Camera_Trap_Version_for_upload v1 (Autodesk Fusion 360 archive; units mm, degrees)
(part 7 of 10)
offset_faces "OffsetFaces4" distance -2
position "Position37"
sketch "Sketch4" plane through (-21, 0, 0) normal (1, 0, 0) x axis (0, 1, 0)
  circle C1 centre (-38.4779, 86.3786) radius 7
  circle C2 centre (-38.4779, 86.3786) radius 5.075
  concentric C1 C2
  dimension "d1453" diameter C2 = 10.15
extrude "Extrude8" add sketch "Sketch4" along normal blind 4
sketch "Sketch5" plane through (-21, 0, 0) normal (1, 0, 0) x axis (0, 1, 0)
  circle C1 centre (-38.4779, 196.3786) radius 7
  circle C2 centre (-38.4779, 196.3786) radius 5.075
  concentric C1 C2
  dimension "d1456" diameter C2 = 10.15
extrude "Extrude9" add sketch "Sketch5" along normal blind 4
sketch "Battery_Cap" plane through (132, 0, 0) normal (1, 0, 0) x axis (0, 1, 0)
  curve K1 (30.3781, 72.1723) -> (-16.7801, 97.9933)
  curve K2 (-31.7648, 74.3864) -> (11.6713, 42.7017)
  line L1 (-24.6413, 218.3549) -> (-24.6413, 188.3549)
  line L2 (15.3587, 228.3549) -> (-14.6413, 228.3549)
  line L3 (25.3587, 188.3549) -> (25.3587, 218.3549)
  line L4 (-14.6413, 178.3549) -> (15.3587, 178.3549)
  curve K3 (-41.7381, 92.8101) -> (-42.0981, 81.8831)
  curve K4 (-35.4016, 81.8831) -> (-35.7616, 92.8101)
  curve K5 (-41.7381, 202.8101) -> (-42.0981, 191.8831)
  curve K6 (-35.4016, 191.8831) -> (-35.7616, 202.8101)
  line L5 (-18, 145) -> (-18, 127)
  line L6 (33, 153) -> (-10, 153)
  line L7 (41, 127) -> (41, 145)
  line L8 (-10, 119) -> (33, 119)
  line L9 (33, 28) -> (2.8201, 28)
  line L10 (53, 28) -> (33, 28)
  line L11 (53, 253.2053) -> (53, 28)
  line L12 (-35.395, 253.2053) -> (53, 253.2053)
  curve K7 (-35.395, 253.2053) -> (-39.3474, 235.851)
  line L13 (-24.9659, 145) -> (-24.9659, 127)
  line L14 (-10, 112.0341) -> (33, 112.0341)
  line L15 (47.9659, 127) -> (47.9659, 145)
  line L16 (33, 159.9659) -> (-10, 159.9659)
  line L17 (33, 152) -> (-10, 152)
  line L18 (-17, 145) -> (-17, 127)
  line L19 (-10, 120) -> (33, 120)
  line L20 (33, 151) -> (-10, 151)
  line L21 (-16, 145) -> (-16, 127)
  line L22 (-10, 121) -> (33, 121)
  line L23 (39, 135) -> (-16, 135)
  line L24 (41, 137.5) -> (39, 137.5)
  line L25 (39, 132.5) -> (41, 132.5)
  line L26 (39, 137.5) -> (39, 145)
  line L27 (39, 127) -> (39, 132.5)
  line L28 (40, 137.5) -> (40, 145)
  line L29 (40, 127) -> (40, 132.5)
  circle C1 centre (0.3587, 230.8549) radius 1
  circle C2 centre (-27.1413, 203.3549) radius 1
  circle C3 centre (0.3587, 175.8549) radius 1
  circle C4 centre (27.8587, 203.3549) radius 1
  arc A1 centre (0.3587, 70.5549) radius 30.0629 clockwise from (30.3781, 72.1723) to (11.6713, 42.7017)
  arc A2 centre (0.3587, 70.5549) radius 32.3513 clockwise from (-31.7648, 74.3864) to (-16.7801, 97.9933)
  arc A3 centre (-14.6413, 218.3549) radius 10 clockwise from (-24.6413, 218.3549) to (-14.6413, 228.3549)
  arc A4 centre (15.3587, 218.3549) radius 10 clockwise from (15.3587, 228.3549) to (25.3587, 218.3549)
  arc A5 centre (15.3587, 188.3549) radius 10 clockwise from (25.3587, 188.3549) to (15.3587, 178.3549)
  arc A6 centre (-14.6413, 188.3549) radius 10 clockwise from (-14.6413, 178.3549) to (-24.6413, 188.3549)
  arc A7 centre (-38.7498, 86.5785) radius 6.911 clockwise from (-41.7381, 92.8101) to (-35.7616, 92.8101)
  arc A8 centre (-38.7498, 86.5785) radius 5.767 clockwise from (-35.4016, 81.8831) to (-42.0981, 81.8831)
  arc A9 centre (-38.7498, 196.5785) radius 6.911 clockwise from (-41.7381, 202.8101) to (-35.7616, 202.8101)
  arc A10 centre (-38.7498, 196.5785) radius 5.767 clockwise from (-35.4016, 191.8831) to (-42.0981, 191.8831)
  circle C5 centre (39.9595, 118.7954) radius 1.4
  circle C6 centre (39.9595, 153.2046) radius 1.4
  circle C7 centre (-16.9412, 117.9586) radius 1.4
  circle C8 centre (-17.953, 152.353) radius 1.4
  arc A11 centre (-10, 127) radius 8 clockwise from (-10, 119) to (-18, 127)
  arc A12 centre (-10, 145) radius 8 clockwise from (-18, 145) to (-10, 153)
  arc A13 centre (33, 145) radius 8 clockwise from (33, 153) to (41, 145)
  arc A14 centre (33, 127) radius 8 clockwise from (41, 127) to (33, 119)
  arc A15 centre (0, 205) radius 50 clockwise from (-40.632, 175.8617) to (-39.3474, 235.851)
  arc A16 centre (-81.264, 146.7234) radius 50 clockwise from (-40.632, 175.8617) to (-31.815, 139.3208)
  arc A17 centre (-1.7685, 134.8228) radius 30.3814 clockwise from (-32.1436, 135.4388) to (-31.815, 139.3208)
  arc A18 centre (-82.1333, 136.4527) radius 50 clockwise from (-32.1436, 135.4388) to (-40.4895, 108.7798)
  arc A19 centre (2.8201, 80) radius 52 clockwise from (2.8201, 28) to (-40.4895, 108.7798)
  arc A20 centre (-10, 145) radius 14.9659 clockwise from (-24.9659, 145) to (-10, 159.9659)
  arc A21 centre (-10, 127) radius 14.9659 clockwise from (-10, 112.0341) to (-24.9659, 127)
  arc A22 centre (33, 127) radius 14.9659 clockwise from (47.9659, 127) to (33, 112.0341)
  arc A23 centre (33, 145) radius 14.9659 clockwise from (33, 159.9659) to (47.9659, 145)
  arc A24 centre (33, 145) radius 7 clockwise from (33, 152) to (40, 145)
  arc A25 centre (-10, 145) radius 7 clockwise from (-17, 145) to (-10, 152)
  arc A26 centre (-10, 127) radius 7 clockwise from (-10, 120) to (-17, 127)
  arc A27 centre (33, 127) radius 7 clockwise from (40, 127) to (33, 120)
  arc A28 centre (33, 145) radius 6 clockwise from (33, 151) to (39, 145)
  arc A29 centre (-10, 145) radius 6 clockwise from (-16, 145) to (-10, 151)
  arc A30 centre (-10, 127) radius 6 clockwise from (-10, 121) to (-16, 127)
  arc A31 centre (33, 127) radius 6 clockwise from (39, 127) to (33, 121)
  point P100 (-16, 135)
  point P101 (39, 135)
  point P104 (41, 132.5)
  point P106 (40, 137.5)
  point P107 (40, 132.5)
  coincident L21 P100
  coincident P101 L26
  perpendicular L23 L26
  horizontal L24
  horizontal L25
  coincident L7 P104
  concentric A13 A28
  concentric A12 A29
  concentric A11 A30
  concentric A14 A31
  tangent L22 A31
  tangent A31 L26
  tangent A30 L22
  tangent A29 L21
  tangent L20 A29
  tangent L21 A30
  tangent A28 L20
  tangent A28 L26
  collinear L26 L27
  concentric A13 A24
  concentric A12 A25
  concentric A11 A26
  concentric A14 A27
  tangent A26 L19
  tangent L19 A27
  tangent L17 A25
  tangent A24 L17
  tangent L18 A26
  tangent A25 L18
  tangent A27 L28
  tangent A24 L28
  coincident L24 P106
  coincident L25 P107
  collinear L28 L29
  dimension "d1459" = -6.9659
extrude "Extrude20" new body sketch "Battery_Cap" profile of C5 C6 C7 C8 A11 L5 A12 L6 A13 L7 A14 L8 L16 A23 A22 A20 L15 L13 A21 L14 along normal blind 3 bodies "Battery_lid_complete"
extrude "Extrude21" new body sketch "Battery_Cap" profile of A24 A27 L17 L18 A26 L29 A25 L19 L22 A31 A29 L20 L27 A30 L21 A28 L24 L25 against normal blind 15 bodies "Battery_lid_wall"
fillet "Fillet1" radius 0.5
combine "Combine15"
extrude "Extrude22" cut of existing geometry blind -5
extrude "Extrude23" cut of existing geometry blind -5
sketch "Sketch2" plane through (0, 31, 0) normal (0, -1, 0) x axis (1, 0, 0)
  line L1 (66, 245) -> (66, 158)
  line L2 (120, 245) -> (66, 245)
  line L3 (120, 158) -> (120, 245)
  line L4 (66, 158) -> (120, 158)
  line L5 (123, 155) -> (63, 155)
  line L6 (123, 248) -> (123, 155)
  line L7 (63, 248) -> (123, 248)
  line L8 (63, 155) -> (63, 248)
  line L9 (123, 248) -> (63, 248)
  line L10 (63, 155) -> (123, 155)
  line L11 (63, 248) -> (63, 155)
  line L12 (114, 158) -> (114, 158)
  line L13 (120, 158) -> (120, 158)
  line L14 (120, 245) -> (66, 245)
  line L15 (120, 158) -> (120, 245)
  line L16 (66, 158) -> (120, 158)
  line L17 (66, 245) -> (66, 158)
  line L18 (66.5, 158.5) -> (119.5, 158.5)
  line L19 (66.5, 244.5) -> (66.5, 158.5)
  line L20 (119.5, 244.5) -> (66.5, 244.5)
  line L21 (119.5, 158.5) -> (119.5, 244.5)
  line L22 (123, 248) -> (63, 248)
  line L23 (123, 155) -> (123, 248)
  line L24 (63, 155) -> (123, 155)
  line L25 (63, 248) -> (63, 155)
  line L26 (105.3133, 127.0783) -> (105.3133, 145.0783)
  line L27 (125.3133, 145.0783) -> (125.3133, 135.0783)
  line L28 (125.3133, 135.0783) -> (125.3133, 127.0783)
  line L29 (105.3133, 145.0783) -> (105.3133, 158.6452)
  line L30 (125.3133, 158.6452) -> (105.3133, 158.6452)
  line L31 (125.3133, 158.6452) -> (125.3133, 145.0783)
  line L32 (105.3133, 113.5114) -> (105.3133, 127.0783)
  line L33 (125.3133, 127.0783) -> (125.3133, 113.5114)
  line L34 (125.3133, 113.5114) -> (105.3133, 113.5114)
  circle C1 centre (69, 242) radius 1.5
  circle C2 centre (117, 242) radius 1.5
  circle C3 centre (117, 161) radius 1.5
  circle C4 centre (69, 161) radius 1.5
  point P7 (123, 155)
  point P12 (123, 155)
  point P9 (63, 248)
  point P10 (63, 248)
  point P16 (114, 158)
  point P5 (120, 158)
  point P14 (120, 158)
  point P3 (66, 245)
  point P18 (66, 245)
  horizontal L9
  horizontal L10
  vertical L11
  coincident P7 P12
  coincident P9 P10
  coincident L4 P16
  coincident P5 P14
  horizontal L14
  vertical L15
  horizontal L16
  vertical L17
  coincident P3 P18
  horizontal L22
  vertical L23
  horizontal L24
  vertical L25
  dimension "d1473" = 0.5
extrude "Extrude5" cut of existing geometry to an object
extrude "Extrude6" add of existing geometry to an object
extrude "Extrude10" new body sketch "Sketch2" profile of L1 L2 L3 L4 L5 L6 L7 L8 L9 L10 L11 L14 L15 L16 L17 L19 L20 L18 L21 C1 C2 C3 C4 L22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 along normal blind 3
extrude "Extrude11" new body sketch "Sketch2" profile of L19 L20 L18 L21 C1 C2 C3 C4 against normal blind 2.7 bodies "Electronic_lid"
combine "Combine7"
fillet "Fillet1" radius 0.5
combine "Combine8"
sketch "Sketch10" plane through (-17.1975, 0, 0) normal (-1, 0, 0) x axis (0, -1, 0)
  line L1 (-18, 105) -> (-45.508, 105)
  line L2 (-15, 176.0417) -> (-15, 108)
  line L3 (-45.508, 179.0417) -> (-18, 179.0417)
  line L4 (-48.508, 108) -> (-48.508, 176.0417)
  line L5 (-15, 174.0406) -> (-48.508, 174.0406)
  line L6 (-15.297, 174.0406) -> (-48.297, 174.0406)
  line L7 (-15.297, 117.0406) -> (-15.297, 174.0406)
  line L8 (-48.297, 117.0406) -> (-15.297, 117.0406)
  line L9 (-48.297, 174.0406) -> (-48.297, 117.0406)
  circle C1 centre (-19, 176.786) radius 1.4
  circle C2 centre (-45, 107.4) radius 1.4
  circle C3 centre (-45, 176.786) radius 1.4
  circle C4 centre (-19, 107.4) radius 1.4
  arc A1 centre (-45.508, 108) radius 3 clockwise from (-45.508, 105) to (-48.508, 108)
  arc A2 centre (-18, 108) radius 3 clockwise from (-15, 108) to (-18, 105)
  arc A3 centre (-18, 176.0417) radius 3 clockwise from (-18, 179.0417) to (-15, 176.0417)
  arc A4 centre (-45.508, 176.0417) radius 3 clockwise from (-48.508, 176.0417) to (-45.508, 179.0417)
  point P18 (-48.508, 174.0406)
  point P19 (-15, 174.0406)
  point P20 (-48.297, 174.0406)
  point P21 (-15.297, 174.0406)
  point P23 (-48.297, 117.0406)
  coincident L4 P18
  coincident L2 P19
  perpendicular L2 L5
  horizontal L6
  vertical L7
  horizontal L8
  vertical L9
  coincident L5 P20
  dimension "d1484" distance P20 P21 = 33
  dimension "d1485" distance P20 P23 = 57
extrude "Extrude10" cut sketch "Sketch10" profile of L5 L6 L7 L8 L9 against normal blind 2
sketch "Sketch11" plane through (-17.1975, 0, 0) normal (-1, 0, 0) x axis (0, -1, 0)
  line L1 (-15.297, 117.0406) -> (-15.297, 174.0406)
  line L2 (-48.297, 117.0406) -> (-15.297, 117.0406)
  line L3 (-48.297, 174.0406) -> (-48.297, 117.0406)
  line L4 (-15.297, 174.0406) -> (-48.297, 174.0406)
  line L5 (-18, 105) -> (-45.508, 105)
  line L6 (-15, 176.0417) -> (-15, 108)
  line L7 (-45.508, 179.0417) -> (-18, 179.0417)
  line L8 (-48.508, 108) -> (-48.508, 176.0417)
  line L9 (-21, 117.0406) -> (-41.6953, 117.0406)
  line L10 (-21, 110.57) -> (-21, 117.0406)
  line L11 (-41.6953, 110.57) -> (-21, 110.57)
  line L12 (-41.6953, 117.0406) -> (-41.6953, 110.57)
  circle C1 centre (-19, 176.786) radius 1.4
  circle C2 centre (-45, 107.4) radius 1.4
  circle C3 centre (-45, 176.786) radius 1.4
  circle C4 centre (-19, 107.4) radius 1.4
  arc A1 centre (-45.508, 108) radius 3 clockwise from (-45.508, 105) to (-48.508, 108)
  arc A2 centre (-18, 108) radius 3 clockwise from (-15, 108) to (-18, 105)
  arc A3 centre (-18, 176.0417) radius 3 clockwise from (-18, 179.0417) to (-15, 176.0417)
  arc A4 centre (-45.508, 176.0417) radius 3 clockwise from (-48.508, 176.0417) to (-45.508, 179.0417)
  point P22 (-41.6953, 117.0406)
  horizontal L9
  vertical L10
  horizontal L11
  vertical L12
  coincident L2 P22
extrude "Extrude11" cut sketch "Sketch11" profile of L2 L9 L10 L11 L12 against normal blind 4
external_derived "ExternalDerived5"
modify "Modify1"
modify "Modify2"
modify "Modify3"
modify "Modify4"
external_derived "ExternalDerived6"
move "Move7"
move_face "MoveFace1"
move "Move8"
move "Move9"
sketch "Sketch12" plane through (-23.4, 0, 0) normal (-1, 0, 0) x axis (0, -1, 0)
  line L1 (-35.3087, 168.4587) -> (-22.4913, 168.4587)
  line L2 (-35.3087, 135.6413) -> (-35.3087, 168.4587)
  line L3 (-22.4913, 135.6413) -> (-35.3087, 135.6413)
  line L4 (-22.4913, 168.4587) -> (-22.4913, 135.6413)
  line L5 (-21, 170) -> (-37, 170)
  line L6 (-21, 134) -> (-21, 170)
  line L7 (-37, 134) -> (-21, 134)
  line L8 (-37, 170) -> (-37, 134)
  line L9 (-30.895, 154.3118) -> (-27.4, 154.3118)
  curve K1 (-30.895, 154.3118) -> (-33.6332, 157.05)
  line L10 (-33.6332, 160.45) -> (-33.6332, 157.05)
  curve K2 (-33.6332, 160.45) -> (-30.895, 163.1882)
  line L11 (-27.4, 163.1882) -> (-30.895, 163.1882)
  curve K3 (-27.4, 163.1882) -> (-24.6618, 160.45)
  line L12 (-24.6618, 157.05) -> (-24.6618, 160.45)
  curve K4 (-24.6618, 157.05) -> (-27.4, 154.3118)
  line L13 (-30.8586, 142.0634) -> (-27.3636, 142.0755)
  curve K5 (-30.8586, 142.0634) -> (-33.6062, 144.7922)
  line L14 (-33.6179, 148.1921) -> (-33.6062, 144.7922)
  curve K6 (-33.6179, 148.1921) -> (-30.8892, 150.9398)
  line L15 (-27.3942, 150.9518) -> (-30.8892, 150.9398)
  curve K7 (-27.3942, 150.9518) -> (-24.6466, 148.2231)
  line L16 (-24.6348, 144.8231) -> (-24.6466, 148.2231)
  curve K8 (-24.6348, 144.8231) -> (-27.3636, 142.0755)
  horizontal L5
  vertical L6
  horizontal L7
  vertical L8
extrude "Extrude12" add of existing geometry blind 3
sketch "Sketch13" plane through (-20.1975, 0, 0) normal (-1, 0, 0) x axis (0, -1, 0)
  line L1 (-41.6953, 117.0406) -> (-41.6953, 110.57)
  line L2 (-48.297, 117.0406) -> (-41.6953, 117.0406)
  line L3 (-48.297, 174.0406) -> (-48.297, 117.0406)
  line L4 (-15.297, 174.0406) -> (-48.297, 174.0406)
  line L5 (-15.297, 117.0406) -> (-15.297, 174.0406)
  line L6 (-21, 117.0406) -> (-15.297, 117.0406)
  line L7 (-21, 110.57) -> (-21, 117.0406)
  line L8 (-41.6953, 110.57) -> (-21, 110.57)
  curve K1 (36.0257, 253.4503) -> (39.9781, 236.096)
  line L9 (-52.3693, 253.4503) -> (36.0257, 253.4503)
  line L10 (-52.3693, 28.245) -> (-52.3693, 253.4503)
  line L11 (-32.3693, 28.245) -> (-52.3693, 28.245)
  line L12 (-2.1894, 28.245) -> (-32.3693, 28.245)
  line L13 (-34.3693, 194.245) -> (-34.3693, 213.245)
  line L14 (-41.3693, 194.245) -> (-34.3693, 194.245)
  line L15 (-41.3693, 213.245) -> (-41.3693, 194.245)
  line L16 (-34.3693, 213.245) -> (-41.3693, 213.245)
  line L17 (-16.019, 180) -> (-47, 180)
  line L18 (-13.019, 107.5562) -> (-13.019, 177)
  line L19 (-48, 104.5562) -> (-16.019, 104.5562)
  line L20 (-50, 177) -> (-50, 106.5562)
  line L21 (-21, 170) -> (-37, 170)
  line L22 (-21, 134) -> (-21, 170)
  line L23 (-37, 134) -> (-21, 134)
  line L24 (-37, 170) -> (-37, 134)
  circle C1 centre (-19, 107.4) radius 1.4
  circle C2 centre (-45, 176.786) radius 1.4
  circle C3 centre (-45, 107.4) radius 1.4
  circle C4 centre (-19, 176.786) radius 1.4
  arc A1 centre (-2.1894, 80.245) radius 52 clockwise from (41.1202, 109.0248) to (-2.1894, 28.245)
  arc A2 centre (82.764, 136.6977) radius 50 clockwise from (41.1202, 109.0248) to (32.7743, 135.6838)
  arc A3 centre (2.3992, 135.0677) radius 30.3814 clockwise from (32.4457, 139.5658) to (32.7743, 135.6838)
  arc A4 centre (81.8947, 146.9684) radius 50 clockwise from (32.4457, 139.5658) to (41.2627, 176.1067)
  arc A5 centre (0.6307, 205.245) radius 50 clockwise from (39.9781, 236.096) to (41.2627, 176.1067)
  arc A6 centre (-47, 177) radius 3 clockwise from (-50, 177) to (-47, 180)
  arc A7 centre (-16.019, 177) radius 3 clockwise from (-16.019, 180) to (-13.019, 177)
  arc A8 centre (-16.019, 107.5562) radius 3 clockwise from (-13.019, 107.5562) to (-16.019, 104.5562)
  arc A9 centre (-48, 106.5562) radius 2 clockwise from (-48, 104.5562) to (-50, 106.5562)
  horizontal L17
  vertical L18
  horizontal L19
  vertical L20
  tangent L17 A6
  tangent L20 A6
  tangent L17 A7
  tangent L18 A7
  tangent L18 A8
  tangent L19 A8
  tangent L20 A9
  tangent L19 A9
  horizontal L21
  vertical L22
  horizontal L23
  vertical L24
  dimension "d1492" radius A6 = 3
  dimension "d1493" radius A7 = 3
  dimension "d1494" radius A8 = 3
  dimension "d1495" radius A9 = 2
extrude "Extrude5" add sketch "Sketch12" along normal blind 1
extrude "Extrude7" add sketch "Sketch13" profile of C1 C2 C3 C4 L1 L2 L3 L4 L5 L6 L7 L8 L17 L18 L19 L20 A6 A7 A8 A9 L21 L22 L23 L24 against normal blind 3
sketch "Sketch14" plane through (-17.1975, 0, 0) normal (1, 0, 0) x axis (0, 1, 0)
  line L1 (21, 134) -> (37, 134)
  line L2 (21, 170) -> (21, 134)
  line L3 (37, 170) -> (21, 170)
  line L4 (37, 134) -> (37, 170)
  line L5 (16.019, 180) -> (47, 180)
  line L6 (13.019, 107.5562) -> (13.019, 177)
  line L7 (48, 104.5562) -> (16.019, 104.5562)
  line L8 (50, 177) -> (50, 106.5562)
  circle C1 centre (45, 107.4) radius 1.4
  circle C2 centre (19, 176.7861) radius 1.4
  circle C3 centre (19, 107.4) radius 1.4
  circle C4 centre (45, 176.7861) radius 1.4
  arc A1 centre (47, 177) radius 3 clockwise from (47, 180) to (50, 177)
  arc A2 centre (16.019, 177) radius 3 clockwise from (13.019, 177) to (16.019, 180)
  arc A3 centre (16.019, 107.5562) radius 3 clockwise from (16.019, 104.5562) to (13.019, 107.5562)
  arc A4 centre (48, 106.5562) radius 2 clockwise from (50, 106.5562) to (48, 104.5562)
sketch "Sketch15" plane through (-20.1975, 0, 0) normal (-1, 0, 0) x axis (0, -1, 0)
  line L1 (-37, 134) -> (-21, 134)
  line L2 (-37, 170) -> (-37, 134)
  line L3 (-21, 170) -> (-37, 170)
  line L4 (-21, 134) -> (-21, 170)
  line L5 (-50, 106.5562) -> (-50, 177)
  line L6 (-16.019, 104.5562) -> (-48, 104.5562)
  line L7 (-13.019, 177) -> (-13.019, 107.5562)
  line L8 (-47, 180) -> (-16.019, 180)
  line L9 (-22, 130) -> (-40, 130)
  line L10 (-22, 117) -> (-22, 130)
  line L11 (-40, 117) -> (-22, 117)
  line L12 (-40, 130) -> (-40, 117)
  circle C1 centre (-45, 107.4) radius 1.4
  circle C2 centre (-19, 176.7861) radius 1.4
  circle C3 centre (-19, 107.4) radius 1.4
  circle C4 centre (-45, 176.7861) radius 1.4
  arc A1 centre (-47, 177) radius 3 clockwise from (-50, 177) to (-47, 180)
  arc A2 centre (-48, 106.5562) radius 2 clockwise from (-48, 104.5562) to (-50, 106.5562)
  arc A3 centre (-16.019, 107.5562) radius 3 clockwise from (-13.019, 107.5562) to (-16.019, 104.5562)
  arc A4 centre (-16.019, 177) radius 3 clockwise from (-16.019, 180) to (-13.019, 177)
  horizontal L9
  vertical L10
  horizontal L11
  vertical L12
extrude "Extrude3" cut sketch "Sketch15" profile of L9 L10 L11 L12 blind -1.5 from offset -1
extrude "Extrude4" add of existing geometry blind 4
work_plane "WorkPlane1" AlongDistance 0
sketch "Sketch1" plane through (-19, 0, 0) normal (-1, 0, 0) x axis (0, -1, 0)
  line L1 (-24, 162) -> (-36, 162)
  line L2 (-24, 155) -> (-24, 162)
  line L3 (-36, 155) -> (-24, 155)
  line L4 (-36, 162) -> (-36, 155)
  line L5 (-24, 150) -> (-36, 150)
  line L6 (-24, 143) -> (-24, 150)
  line L7 (-36, 143) -> (-24, 143)
  line L8 (-36, 150) -> (-36, 143)
  line L9 (-22, 130) -> (-41, 130)
  line L10 (-22, 117) -> (-22, 130)
  line L11 (-41, 117) -> (-22, 117)
  line L12 (-41, 130) -> (-41, 117)
  line L13 (-37.3355, 150) -> (-40, 150)
  line L14 (-37.3355, 145.4939) -> (-37.3355, 150)
  line L15 (-40, 145.4939) -> (-37.3355, 145.4939)
  line L16 (-40, 150) -> (-40, 145.4939)
  line L17 (-33, 141) -> (-36, 141)
  line L18 (-33, 136) -> (-33, 141)
  line L19 (-36, 136) -> (-33, 136)
  line L20 (-36, 141) -> (-36, 136)
  line L21 (-16, 173) -> (-49, 173)
  line L22 (-16, 116.4339) -> (-16, 173)
  line L23 (-49, 116.4339) -> (-16, 116.4339)
  line L24 (-49, 173) -> (-49, 116.4339)
  horizontal L1
  vertical L2
  horizontal L3
  vertical L4
  horizontal L5
  vertical L6
  horizontal L7
  vertical L8
  horizontal L9
  vertical L10
  horizontal L11
  vertical L12
  horizontal L13
  vertical L14
  horizontal L15
  vertical L16
  horizontal L17
  vertical L18
  horizontal L19
  vertical L20
  horizontal L21
  vertical L22
  horizontal L23
  vertical L24
extrude "Extrude2" new body sketch "Sketch1" profile of L9 L10 L11 L12 along normal blind 4.5
extrude "Extrude3" new body sketch "Sketch1" profile of L13 L14 L15 L16 L17 L18 L19 L20 along normal blind 1
extrude "Extrude4" new body sketch "Sketch1" to an object
combine "Combine2"
extrude "Extrude6" cut of existing geometry to an object
extrude "Extrude7" add of existing geometry blind 1
sketch "Sketch2" plane through (-25.2025, 0, 0) normal (-1, 0, 0) x axis (0, -1, 0)
  line L1 (-22.0307, 135.3012) -> (-22.0307, 168.3088)
  line L2 (-36.0345, 134.305) -> (-23.0269, 134.305)
  line L3 (-37.0307, 168.3088) -> (-37.0307, 135.3012)
  line L4 (-23.0269, 169.305) -> (-36.0345, 169.305)
  line L5 (-49, 116.4339) -> (-49, 173)
  line L6 (-16, 116.4339) -> (-49, 116.4339)
  line L7 (-16, 173) -> (-16, 116.4339)
  line L8 (-49, 173) -> (-16, 173)
  line L9 (-23, 170.5557) -> (-36, 170.5557)
  line L10 (-21, 135) -> (-21, 168.5557)
  line L11 (-36, 133) -> (-23, 133)
  line L12 (-38, 168.5557) -> (-38, 135)
  line L13 (-23.1242, 168.2129) -> (-35.9366, 168.2129)
  line L14 (-23.1242, 135.4031) -> (-23.1242, 168.2129)
  line L15 (-35.9366, 135.4031) -> (-23.1242, 135.4031)
  line L16 (-35.9366, 168.2129) -> (-35.9366, 135.4031)
  closed curve K1 centre (-23.0345, 135.3088)
  closed curve K2 centre (-36.0269, 135.3088)
  closed curve K3 centre (-36.0269, 168.3012)
  closed curve K4 centre (-23.0345, 168.3012)
  arc A1 centre (-36, 168.5557) radius 2 clockwise from (-38, 168.5557) to (-36, 170.5557)
  arc A2 centre (-23, 168.5557) radius 2 clockwise from (-23, 170.5557) to (-21, 168.5557)
  arc A3 centre (-36, 135) radius 2 clockwise from (-36, 133) to (-38, 135)
  arc A4 centre (-23, 135) radius 2 clockwise from (-21, 135) to (-23, 133)
  horizontal L9
  vertical L10
  horizontal L11
  vertical L12
  tangent L12 A1
  tangent L9 A1
  tangent L9 A2
  tangent L10 A2
  tangent L12 A3
  tangent L11 A3
  tangent L10 A4
  tangent L11 A4
  horizontal L13
  vertical L14
  horizontal L15
  vertical L16
  dimension "d1524" radius A1 = 2
  dimension "d1525" radius A2 = 2
  dimension "d1526" radius A3 = 2
  dimension "d1527" radius A4 = 2
extrude "Extrude8" add sketch "Sketch2" profile of L1 K1 L2 K2 L3 K3 L4 K4 L9 L10 L11 L12 A1 A2 A3 A4 L13 L14 L15 L16 along normal blind 3
extrude "Extrude9" cut sketch "Sketch1" along normal blind 0.5
extrude "Extrude10" add of existing geometry blind 3
extrude "Extrude11" cut of existing geometry blind -2
extrude "Extrude13" cut of existing geometry blind -0.6
extrude "Extrude14" add of existing geometry blind 1.5
extrude "Extrude15" add of existing geometry blind 3
extrude "Extrude16" add of existing geometry blind 3
extrude "Extrude17" add of existing geometry blind 1.5
sketch "Sketch3" plane through (-19.5, 0, 0) normal (1, 0, 0) x axis (0, 1, 0)
  line L1 (41, 113.4339) -> (41, 130)
  line L2 (50.5, 113.4339) -> (41, 113.4339)
  line L3 (50.5, 176) -> (50.5, 113.4339)
  line L4 (14.5, 176) -> (50.5, 176)
  line L5 (14.5, 113.4339) -> (14.5, 176)
  line L6 (22, 113.4339) -> (14.5, 113.4339)
  line L7 (22, 130) -> (22, 113.4339)
  line L8 (41, 130) -> (22, 130)
  line L9 (22.0307, 168.3088) -> (22.0307, 135.3012)
  line L10 (36.0345, 169.305) -> (23.0269, 169.305)
  line L11 (37.0307, 135.3012) -> (37.0307, 168.3088)
  line L12 (23.0269, 134.305) -> (36.0345, 134.305)
  line L13 (40, 145.4939) -> (40, 150)
  line L14 (37.3355, 145.4939) -> (40, 145.4939)
  line L15 (37.3355, 150) -> (37.3355, 145.4939)
  line L16 (40, 150) -> (37.3355, 150)
  line L17 (48.602, 173.305) -> (16.12, 173.305)
  line L18 (48.602, 117.7187) -> (48.602, 173.305)
  line L19 (16.12, 117.7187) -> (48.602, 117.7187)
  line L20 (16.12, 173.305) -> (16.12, 117.7187)
  line L21 (49.102, 117.2187) -> (49.102, 173.805)
  line L22 (15.62, 117.2187) -> (49.102, 117.2187)
  line L23 (15.62, 173.805) -> (15.62, 117.2187)
  line L24 (49.102, 173.805) -> (15.62, 173.805)
  closed curve K1 centre (23.0345, 168.3012)
  closed curve K2 centre (36.0269, 168.3012)
  closed curve K3 centre (36.0269, 135.3088)
  closed curve K4 centre (23.0345, 135.3088)
  horizontal L17
  vertical L18
  horizontal L19
  vertical L20
  dimension "d1548" = -0.5
extrude "Extrude19" add of existing geometry blind 8
sketch "Sketch5" plane through (0, 0, 105.4339) normal (0, 0, -1) x axis (1, 0, 0)
  line L1 (-23.5, -41) -> (-19.5, -41)
  line L2 (-23.5, -22) -> (-23.5, -41)
  line L3 (-19.5, -22) -> (-23.5, -22)
  line L4 (-19.5, -14.5) -> (-19.5, -22)
  line L5 (-28.2025, -14.5) -> (-19.5, -14.5)
  line L6 (-28.2025, -50.5) -> (-28.2025, -14.5)
  line L7 (-19.5, -50.5) -> (-28.2025, -50.5)
  line L8 (-19.5, -41) -> (-19.5, -50.5)
  line L9 (-23.5, -41) -> (-19.5, -41)
  line L10 (-23.5, -22) -> (-23.5, -41)
  line L11 (-19.5, -22) -> (-23.5, -22)
  line L12 (-19.5, -41) -> (-19.5, -22)
  point P4 (-23.5, -22)
  point P12 (-23.5, -22)
  point P2 (-19.5, -41)
  point P10 (-19.5, -41)
  horizontal L9
  vertical L10
  horizontal L11
  vertical L12
  coincident P4 P12
  coincident P2 P10
extrude "Extrude20" add sketch "Sketch5" profile of L1 L2 L3 L9 L10 L11 L12 against normal blind 5
extrude "Extrude21" cut sketch "Sketch1" along normal blind 1.5
extrude "Extrude22" cut sketch "Sketch1" along normal blind 2
extrude "Extrude23" cut sketch "Sketch1" profile of L13 L14 L15 L16 along normal blind 2
sketch "Sketch16" plane through (0, 52.3693, 0) normal (0, -1, 0) x axis (1, 0, 0)
  line L1 (-20.1975, 30.1667) -> (-20.1975, 253.3719)
  line L2 (135.6399, 30.1667) -> (-20.1975, 30.1667)
  line L3 (135.6399, 253.3719) -> (135.6399, 30.1667)
  line L4 (-20.1975, 253.3719) -> (135.6399, 253.3719)
  line L5 (66.4892, 182.0802) -> (-13.5883, 182.0802)
  line L6 (66.4892, 248.1667) -> (66.4892, 182.0802)
  line L7 (115.6867, 248.1667) -> (66.4892, 248.1667)
  line L8 (115.6867, 245.1667) -> (115.6867, 248.1667)
  line L9 (69.4892, 245.1667) -> (115.6867, 245.1667)
  line L10 (69.4892, 158.1667) -> (69.4892, 245.1667)
  line L11 (105.6867, 158.1667) -> (69.4892, 158.1667)
  line L12 (105.6867, 155.1667) -> (105.6867, 158.1667)
  line L13 (67.9617, 155.1667) -> (105.6867, 155.1667)
  line L14 (67.9617, 105.8632) -> (67.9617, 155.1667)
  line L15 (38.9117, 105.8632) -> (67.9617, 105.8632)
  line L16 (38.9117, 160.0802) -> (38.9117, 105.8632)
  line L17 (-13.5883, 170.0802) -> (28.9117, 170.0802)
  line L18 (-13.5883, 182.0802) -> (-13.5883, 170.0802)
  line L19 (123.4892, 158.1667) -> (115.6867, 158.1667)
  line L20 (123.4892, 248.1667) -> (123.4892, 158.1667)
  line L21 (126.4892, 248.1667) -> (123.4892, 248.1667)
  line L22 (126.4892, 155.1667) -> (126.4892, 248.1667)
  line L23 (115.6867, 155.1667) -> (126.4892, 155.1667)
  line L24 (115.6867, 158.1667) -> (115.6867, 155.1667)
  line L25 (102.4892, 245.1667) -> (69.4892, 245.1667)
  line L26 (102.4892, 158.1667) -> (102.4892, 245.1667)
  line L27 (69.4892, 158.1667) -> (102.4892, 158.1667)
  line L28 (69.4892, 245.1667) -> (69.4892, 158.1667)
  circle C1 centre (113.4892, 230.1667) radius 2.5
  circle C2 centre (113.4892, 50.1667) radius 2.5
  circle C3 centre (1.4892, 230.1667) radius 2.5
  circle C4 centre (1.4892, 50.1667) radius 2.5
  arc A1 centre (28.9117, 160.0802) radius 10 clockwise from (28.9117, 170.0802) to (38.9117, 160.0802)
  circle C5 centre (37.1896, 229.5434) radius 1.4
  point P15 (69.4892, 245.1667)
  point P33 (69.4892, 245.1667)
  point P34 (102.4892, 245.1667)
  point P36 (69.4892, 158.1667)
  horizontal L25
  vertical L26
  horizontal L27
  vertical L28
  coincident P15 P33
  dimension "d1561" distance P33 P34 = 33
  dimension "d1562" distance P33 P36 = 87
sketch "Sketch1" plane through (0, 52.3693, 0) normal (0, -1, 0) x axis (1, 0, 0)
  line L1 (-20.1975, 30.1667) -> (-20.1975, 253.3719)
  line L2 (135.6399, 30.1667) -> (-20.1975, 30.1667)
  line L3 (135.6399, 253.3719) -> (135.6399, 30.1667)
  line L4 (-20.1975, 253.3719) -> (135.6399, 253.3719)
  line L5 (66.4892, 182.0802) -> (-13.5883, 182.0802)
  line L6 (66.4892, 248.1667) -> (66.4892, 182.0802)
  line L7 (115.6867, 248.1667) -> (66.4892, 248.1667)
  line L8 (115.6867, 245.1667) -> (115.6867, 248.1667)
  line L9 (69.4892, 245.1667) -> (115.6867, 245.1667)
  line L10 (69.4892, 158.1667) -> (69.4892, 245.1667)
  line L11 (105.6867, 158.1667) -> (69.4892, 158.1667)
  line L12 (105.6867, 155.1667) -> (105.6867, 158.1667)
  line L13 (67.9617, 155.1667) -> (105.6867, 155.1667)
  line L14 (67.9617, 105.8632) -> (67.9617, 155.1667)
  line L15 (38.9117, 105.8632) -> (67.9617, 105.8632)
  line L16 (38.9117, 160.0802) -> (38.9117, 105.8632)
  line L17 (-13.5883, 170.0802) -> (28.9117, 170.0802)
  line L18 (-13.5883, 182.0802) -> (-13.5883, 170.0802)
  line L19 (123.4892, 158.1667) -> (115.6867, 158.1667)
  line L20 (123.4892, 248.1667) -> (123.4892, 158.1667)
  line L21 (126.4892, 248.1667) -> (123.4892, 248.1667)
  line L22 (126.4892, 155.1667) -> (126.4892, 248.1667)
  line L23 (115.6867, 155.1667) -> (126.4892, 155.1667)
  line L24 (115.6867, 158.1667) -> (115.6867, 155.1667)
  line L25 (102.4892, 245.1667) -> (69.4892, 245.1667)
  line L26 (102.4892, 158.1667) -> (102.4892, 245.1667)
  line L27 (69.4892, 158.1667) -> (102.4892, 158.1667)
  line L28 (69.4892, 245.1667) -> (69.4892, 158.1667)
  line L29 (78, 142) -> (78, 154)
  line L30 (72, 142) -> (78, 142)
  line L31 (81, 125.4307) -> (81, 154)
  line L32 (73.988, 125.4307) -> (81, 125.4307)
  line L33 (80, 163.2506) -> (115, 163.2506)
  line L34 (80, 161.4431) -> (115.6867, 161.4431)
  line L35 (121.3154, 253.3719) -> (121.3154, 165.1767)
  line L36 (123.4892, 214.7568) -> (121.3154, 214.7568)
  line L37 (122.6559, 183.7619) -> (123.4892, 183.7619)
  line L38 (102.4892, 214.7568) -> (102.4892, 183.7619)
  line L39 (122.6559, 253.3719) -> (122.6559, 165.1767)
  line L40 (117.2627, 235) -> (35, 235)
  line L41 (35, 237.1626) -> (117.2627, 237.1626)
  line L42 (83.697, 240) -> (110, 240)
  line L43 (83.7799, 243.1703) -> (110, 243.1703)
  line L44 (84, 241.5358) -> (110, 241.5358)
  line L45 (42, 239) -> (110, 239)
  line L46 (35, 237.775) -> (110, 237.775)
  line L47 (35, 235.7209) -> (110, 235.7209)
  line L48 (42, 234) -> (117, 234)
  line L49 (42, 233) -> (117, 233)
  line L50 (89, 232) -> (117, 232)
  line L51 (88.9995, 230.1667) -> (117.2627, 230.4086)
  line L52 (51, 243) -> (40, 243)
  line L53 (51, 231) -> (51, 243)
  line L54 (40, 231) -> (51, 231)
  line L55 (40, 243) -> (40, 231)
  line L56 (16.0675, 235) -> (35, 235)
  line L57 (16.0675, 107.1197) -> (16.0675, 235)
  line L58 (14, 237.1626) -> (35, 237.1626)
  line L59 (14, 112.5713) -> (14, 237.1626)
  line L60 (10, 237.775) -> (35, 237.775)
  line L61 (10, 116.4185) -> (10, 237.775)
  line L62 (8, 240) -> (42, 239)
  line L63 (7.6617, 118.8836) -> (8, 240)
  line L64 (120, 237.775) -> (104.5725, 237.775)
  line L65 (120, 217) -> (120, 237.775)
  line L66 (104.5725, 217) -> (120, 217)
  line L67 (104.5725, 237.775) -> (104.5725, 217)
  line L68 (7.6441, 112.5713) -> (7.6617, 118.8836)
  line L69 (-10.3245, 112.6215) -> (7.6441, 112.5713)
  line L70 (9.9793, 108.9915) -> (10, 116.4185)
  line L71 (-10.3245, 109.0482) -> (9.9793, 108.9915)
  line L72 (-10.3245, 112.6215) -> (14, 112.5713)
  line L73 (-5.9407, 107.1812) -> (16.0675, 107.1197)
  circle C1 centre (113.4892, 230.1667) radius 2.5
  circle C2 centre (113.4892, 50.1667) radius 2.5
  circle C3 centre (1.4892, 230.1667) radius 2.5
  circle C4 centre (1.4892, 50.1667) radius 2.5
  arc A1 centre (28.9117, 160.0802) radius 10 clockwise from (28.9117, 170.0802) to (38.9117, 160.0802)
  circle C5 centre (37.1896, 229.5434) radius 1.4
  point P15 (69.4892, 245.1667)
  point P33 (69.4892, 245.1667)
  point P48 (121.3154, 253.3719)
  point P51 (123.4892, 183.7619)
  point P49 (102.4892, 214.7568)
  point P54 (122.6559, 253.3719)
  point P91 (104.5725, 237.775)
  point P95 (121.3154, 214.7568)
  point P96 (122.6559, 183.7619)
  point P34 (102.4892, 245.1667)
  point P36 (69.4892, 158.1667)
  horizontal L25
  vertical L26
  horizontal L27
  vertical L28
  coincident P15 P33
  perpendicular L5 L29
  perpendicular L10 L30
  perpendicular L13 L31
  perpendicular L31 L32
  perpendicular L26 L33
  perpendicular L26 L34
  coincident L4 P48
  perpendicular L4 L35
  horizontal L36
  horizontal L37
  vertical L38
  coincident L20 P51
  coincident L26 P49
  coincident L4 P54
  perpendicular L4 L39
  perpendicular L6 L40
  perpendicular L6 L41
  parallel L9 L42
  perpendicular L26 L43
  parallel L42 L44
  perpendicular L6 L45
  perpendicular L26 L46
  parallel L40 L47
  perpendicular L6 L48
  perpendicular L26 L49
  perpendicular L28 L50
  horizontal L52
  vertical L53
  horizontal L54
  vertical L55
  parallel L40 L56
  perpendicular L40 L57
  parallel L41 L58
  perpendicular L58 L59
  parallel L46 L60
  perpendicular L46 L61
  horizontal L64
  vertical L65
  horizontal L66
  vertical L67
  coincident L46 P91
  coincident L35 P95
  coincident L39 P96
  parallel L63 L68
  perpendicular L63 L69
  perpendicular L69 L70
  perpendicular L68 L71
  perpendicular L70 L73
  dimension "d1563" distance P33 P34 = 33
  dimension "d1564" distance P33 P36 = 87
sketch "Sketch3" plane through (63, 0, 0) normal (-1, 0, 0) x axis (0, -1, 0)
  line L1 (-41.6307, 181.9135) -> (-53, 181.9135)
  line L2 (-41.6307, 155) -> (-41.6307, 181.9135)
  line L3 (-31, 155) -> (-41.6307, 155)
  line L4 (-31, 248) -> (-31, 155)
  line L5 (-53, 248) -> (-31, 248)
  line L6 (-53, 181.9135) -> (-53, 248)
  line L7 (-36, 220) -> (-36, 235)
  line L8 (-36, 235) -> (-42.0158, 235)
  line L9 (-42.0158, 220) -> (-36, 220)
  line L10 (-42.0158, 235) -> (-42.0158, 220)
  vertical L7
  horizontal L8
  horizontal L9
  vertical L10
extrude "Extrude12" cut sketch "Sketch3" profile of L7 L8 L9 L10 against normal blind 4
sketch "Sketch4" plane through (63, 0, 0) normal (-1, 0, 0) x axis (0, -1, 0)
  line L1 (-36, 220) -> (-36, 235)
  line L2 (-42.0158, 220) -> (-36, 220)
  line L3 (-42.0158, 235) -> (-42.0158, 220)
  line L4 (-36, 235) -> (-42.0158, 235)
  line L5 (-41.6307, 181.9135) -> (-53, 181.9135)
  line L6 (-41.6307, 155) -> (-41.6307, 181.9135)
  line L7 (-31, 155) -> (-41.6307, 155)
  line L8 (-31, 248) -> (-31, 155)
  line L9 (-53, 248) -> (-31, 248)
  line L10 (-53, 181.9135) -> (-53, 248)
  circle C1 centre (-46, 235) radius 1
  circle C2 centre (-46, 227.5) radius 1
  circle C3 centre (-46, 220) radius 1
  circle C4 centre (12.5214, 224.8325) radius 1
  circle C5 centre (12.5214, 209.8325) radius 1
  circle C6 centre (12.5214, 194.8325) radius 1
  circle C7 centre (12.5214, 179.8325) radius 1
  dimension "d1575" diameter C4 = 2
  dimension "d1571" R-Pattern1-uDistance = 0
  dimension "d1572" R-Pattern1-vDistance = -15
  dimension "d1578" R-Pattern2-uDistance = 0
  dimension "d1579" R-Pattern2-vDistance = -45
extrude "Extrude13" cut sketch "Sketch4" profile of C1 C2 C3 against normal blind 2
sketch "Sketch5" plane through (120, 0, 0) normal (-1, 0, 0) x axis (0, -1, 0)
  line L1 (-34, 164) -> (-42, 164)
  line L2 (-34, 158) -> (-34, 164)
  line L3 (-31, 158) -> (-34, 158)
  line L4 (-31, 245) -> (-31, 158)
  line L5 (-34, 245) -> (-31, 245)
  line L6 (-34, 239) -> (-34, 245)
  line L7 (-42, 239) -> (-34, 239)
  line L8 (-42, 245) -> (-42, 239)
  line L9 (-47.6, 245) -> (-42, 245)
  line L10 (-47.6, 248) -> (-47.6, 245)
  line L11 (-53, 248) -> (-47.6, 248)
  line L12 (-53, 158) -> (-53, 248)
  line L13 (-42, 158) -> (-53, 158)
  line L14 (-42, 164) -> (-42, 158)
  circle C1 centre (-37, 230) radius 1
  circle C2 centre (-37, 205) radius 1
  circle C3 centre (-37, 180) radius 1
  dimension "d1580" diameter C1 = 2
  dimension "d1583" R-Pattern1-uDistance = 0
  dimension "d1584" R-Pattern1-vDistance = -50
extrude "Extrude14" cut sketch "Sketch5" profile of C1 C2 C3 against normal blind 2
extrude "Extrude15" cut of existing geometry blind -2
sketch "Sketch6" plane through (-3.4892, 53, -0.1667) normal (0, -1, 0) x axis (1, 0, 0)
  circle C1 centre (83.2036, 147.979) radius 1
  circle C2 centre (83.2036, 136.979) radius 1
  circle C3 centre (83.2036, 125.979) radius 1
  dimension "d1589" diameter C1 = 2
  dimension "d1592" R-Pattern1-uDistance = 0
  dimension "d1593" R-Pattern1-vDistance = -22
extrude "Extrude16" cut sketch "Sketch6" against normal blind 4
sketch "Sketch7" plane through (-3.4892, 53, -0.1667) normal (0, -1, 0) x axis (1, 0, 0)
  circle C1 centre (105, 170) radius 1
  circle C2 centre (105, 192.5) radius 1
  circle C3 centre (105, 215) radius 1
  dimension "d1596" diameter C1 = 2
  dimension "d1599" R-Pattern1-uDistance = 0
  dimension "d1600" R-Pattern1-vDistance = 45
extrude "Extrude17" cut sketch "Sketch7" against normal blind 4
sketch "Sketch8" plane through (0, 0, 169.9135) normal (0, 0, -1) x axis (1, 0, 0)
  line L1 (25.4225, -53) -> (-17.0775, -53)
  line L2 (25.4225, -41.6307) -> (25.4225, -53)
  line L3 (-17.0775, -41.6307) -> (25.4225, -41.6307)
  line L4 (-17.0775, -53) -> (-17.0775, -41.6307)
  line L5 (14.5574, -53) -> (4.5574, -53)
  line L6 (14.5574, -46) -> (14.5574, -53)
  line L7 (4.5574, -46) -> (14.5574, -46)
  line L8 (4.5574, -53) -> (4.5574, -46)
  point P6 (4.5574, -53)
  point P7 (14.5574, -53)
  horizontal L5
  vertical L6
  horizontal L7
  vertical L8
  coincident L1 P6
  dimension "d1603" distance P6 P7 = 10
extrude "Extrude18" cut sketch "Sketch8" profile of L1 L5 L6 L7 L8 against normal blind 14
sketch "Sketch9" plane through (0, 53, 0) normal (0, -1, 0) x axis (1, 0, 0)
  line L1 (-17.0775, 169.9135) -> (4.5574, 169.9135)
  line L2 (-17.0775, 181.9135) -> (-17.0775, 169.9135)
  line L3 (4.5574, 181.9135) -> (-17.0775, 181.9135)
  line L4 (4.5574, 169.9135) -> (4.5574, 181.9135)
  line L5 (14.5574, 181.9135) -> (14.5574, 169.9135)
  line L6 (63, 181.9135) -> (14.5574, 181.9135)
  line L7 (63, 248) -> (63, 181.9135)
  line L8 (112.1975, 248) -> (63, 248)
  line L9 (112.1975, 245) -> (112.1975, 248)
  line L10 (66, 245) -> (112.1975, 245)
  line L11 (66, 158) -> (66, 245)
  line L12 (102.1975, 158) -> (66, 158)
  line L13 (102.1975, 155) -> (102.1975, 158)
  line L14 (64.4725, 155) -> (102.1975, 155)
  line L15 (64.4725, 105.6965) -> (64.4725, 155)
  line L16 (35.4225, 105.6965) -> (64.4725, 105.6965)
  line L17 (35.4225, 159.9135) -> (35.4225, 105.6965)
  line L18 (14.5574, 169.9135) -> (25.4225, 169.9135)
  line L19 (-23.6867, 30) -> (-23.6867, 253.2053)
  line L20 (132.1507, 30) -> (-23.6867, 30)
  line L21 (132.1507, 253.2053) -> (132.1507, 30)
  line L22 (-23.6867, 253.2053) -> (132.1507, 253.2053)
  line L23 (120, 158) -> (112.1975, 158)
  line L24 (120, 248) -> (120, 158)
  line L25 (123, 248) -> (120, 248)
  line L26 (123, 155) -> (123, 248)
  line L27 (112.1975, 155) -> (123, 155)
  line L28 (112.1975, 158) -> (112.1975, 155)
  arc A1 centre (25.4225, 159.9135) radius 10 clockwise from (25.4225, 169.9135) to (35.4225, 159.9135)
  circle C1 centre (101.5108, 192.3333) radius 1
  circle C2 centre (101.5108, 169.8333) radius 1
  circle C3 centre (101.5108, 214.8333) radius 1
  circle C4 centre (79.7144, 125.8123) radius 1
  circle C5 centre (79.7144, 136.8123) radius 1
  circle C6 centre (79.7144, 147.8123) radius 1
  circle C7 centre (110, 230) radius 2.5
  circle C8 centre (110, 50) radius 2.5
  circle C9 centre (-2, 230) radius 2.5
  circle C10 centre (-2, 50) radius 2.5
  circle C11 centre (33.7003, 229.3768) radius 1.4
  circle C12 centre (45, 219) radius 1
  circle C13 centre (25, 219) radius 1
  circle C14 centre (5, 219) radius 1
  dimension "d1606" diameter C12 = 2
  dimension "d1609" R-Pattern1-uDistance = -45
  dimension "d1610" R-Pattern1-vDistance = 0
  dimension "d1613" R-Pattern2-uDistance = -40
  dimension "d1614" R-Pattern2-vDistance = 0
extrude "Extrude19" cut sketch "Sketch9" profile of C12 C13 C14 against normal blind 4
sketch "Sketch10" plane through (0, 53, 0) normal (0, -1, 0) x axis (1, 0, 0)
  line L1 (-17.0775, 169.9135) -> (4.5574, 169.9135)
  line L2 (-17.0775, 181.9135) -> (-17.0775, 169.9135)
  line L3 (4.5574, 181.9135) -> (-17.0775, 181.9135)
  line L4 (4.5574, 169.9135) -> (4.5574, 181.9135)
  line L5 (14.5574, 181.9135) -> (14.5574, 169.9135)
  line L6 (63, 181.9135) -> (14.5574, 181.9135)
  line L7 (63, 248) -> (63, 181.9135)
  line L8 (112.1975, 248) -> (63, 248)
  line L9 (112.1975, 245) -> (112.1975, 248)
  line L10 (66, 245) -> (112.1975, 245)
  line L11 (66, 158) -> (66, 245)
  line L12 (102.1975, 158) -> (66, 158)
  line L13 (102.1975, 155) -> (102.1975, 158)
  line L14 (64.4725, 155) -> (102.1975, 155)
  line L15 (64.4725, 105.6965) -> (64.4725, 155)
  line L16 (35.4225, 105.6965) -> (64.4725, 105.6965)
  line L17 (35.4225, 159.9135) -> (35.4225, 105.6965)
  line L18 (14.5574, 169.9135) -> (25.4225, 169.9135)
  line L19 (-23.6867, 30) -> (-23.6867, 253.2053)
  line L20 (132.1507, 30) -> (-23.6867, 30)
  line L21 (132.1507, 253.2053) -> (132.1507, 30)
  line L22 (-23.6867, 253.2053) -> (132.1507, 253.2053)
  line L23 (120, 158) -> (112.1975, 158)
  line L24 (120, 248) -> (120, 158)
  line L25 (123, 248) -> (120, 248)
  line L26 (123, 155) -> (123, 248)
  line L27 (112.1975, 155) -> (123, 155)
  line L28 (112.1975, 158) -> (112.1975, 155)
  circle C1 centre (45, 219) radius 1
  circle C2 centre (25, 219) radius 1
  circle C3 centre (5, 219) radius 1
  arc A1 centre (25.4225, 159.9135) radius 10 clockwise from (25.4225, 169.9135) to (35.4225, 159.9135)
  circle C4 centre (101.5108, 192.3333) radius 1
  circle C5 centre (101.5108, 169.8333) radius 1
  circle C6 centre (101.5108, 214.8333) radius 1
  circle C7 centre (79.7144, 125.8123) radius 1
  circle C8 centre (79.7144, 136.8123) radius 1
  circle C9 centre (79.7144, 147.8123) radius 1
  circle C10 centre (110, 230) radius 2.5
  circle C11 centre (110, 50) radius 2.5
  circle C12 centre (-2, 230) radius 2.5
  circle C13 centre (-2, 50) radius 2.5
  circle C14 centre (33.7003, 229.3768) radius 1.4
  circle C15 centre (5, 193) radius 1
  circle C16 centre (5, 163) radius 1
  circle C17 centre (5, 133) radius 1
  dimension "d1617" diameter C15 = 2
  dimension "d1620" R-Pattern1-uDistance = 0
  dimension "d1621" R-Pattern1-vDistance = -60
extrude "Extrude20" cut sketch "Sketch10" profile of C15 C16 C17 against normal blind 4
sketch "Sketch11" plane through (0, 53, 0) normal (0, -1, 0) x axis (1, 0, 0)
  line L1 (-17.0775, 169.9135) -> (4.5574, 169.9135)
  line L2 (-17.0775, 181.9135) -> (-17.0775, 169.9135)
  line L3 (4.5574, 181.9135) -> (-17.0775, 181.9135)
  line L4 (4.5574, 169.9135) -> (4.5574, 181.9135)
  line L5 (14.5574, 181.9135) -> (14.5574, 169.9135)
  line L6 (63, 181.9135) -> (14.5574, 181.9135)
  line L7 (63, 248) -> (63, 181.9135)
  line L8 (112.1975, 248) -> (63, 248)
  line L9 (112.1975, 245) -> (112.1975, 248)
  line L10 (66, 245) -> (112.1975, 245)
  line L11 (66, 158) -> (66, 245)
  line L12 (102.1975, 158) -> (66, 158)
  line L13 (102.1975, 155) -> (102.1975, 158)
  line L14 (64.4725, 155) -> (102.1975, 155)
  line L15 (64.4725, 105.6965) -> (64.4725, 155)
  line L16 (35.4225, 105.6965) -> (64.4725, 105.6965)
  line L17 (35.4225, 159.9135) -> (35.4225, 105.6965)
  line L18 (14.5574, 169.9135) -> (25.4225, 169.9135)
  line L19 (-23.6867, 30) -> (-23.6867, 253.2053)
  line L20 (132.1507, 30) -> (-23.6867, 30)
  line L21 (132.1507, 253.2053) -> (132.1507, 30)
  line L22 (-23.6867, 253.2053) -> (132.1507, 253.2053)
  line L23 (120, 158) -> (112.1975, 158)
  line L24 (120, 248) -> (120, 158)
  line L25 (123, 248) -> (120, 248)
  line L26 (123, 155) -> (123, 248)
  line L27 (112.1975, 155) -> (123, 155)
  line L28 (112.1975, 158) -> (112.1975, 155)
  circle C1 centre (5, 193) radius 1
  circle C2 centre (5, 163) radius 1
  circle C3 centre (5, 133) radius 1
  circle C4 centre (45, 219) radius 1
  circle C5 centre (25, 219) radius 1
  circle C6 centre (5, 219) radius 1
  arc A1 centre (25.4225, 159.9135) radius 10 clockwise from (25.4225, 169.9135) to (35.4225, 159.9135)
  circle C7 centre (101.5108, 192.3333) radius 1
  circle C8 centre (101.5108, 169.8333) radius 1
  circle C9 centre (101.5108, 214.8333) radius 1
  circle C10 centre (79.7144, 125.8123) radius 1
  circle C11 centre (79.7144, 136.8123) radius 1
  circle C12 centre (79.7144, 147.8123) radius 1
  circle C13 centre (110, 230) radius 2.5
  circle C14 centre (110, 50) radius 2.5
  circle C15 centre (-2, 230) radius 2.5
  circle C16 centre (-2, 50) radius 2.5
  circle C17 centre (33.7003, 229.3768) radius 1.4
sketch "Sketch12" plane through (0, 53, 0) normal (0, -1, 0) x axis (1, 0, 0)
  circle C1 centre (5, 110) radius 1
  circle C2 centre (-3, 110) radius 1
  dimension "d1624" diameter C1 = 2
  dimension "d1627" R-Pattern1-uDistance = -8
  dimension "d1628" R-Pattern1-vDistance = 0
extrude "Extrude21" cut sketch "Sketch12" against normal blind 2
extrude "Extrude13" cut of existing geometry blind -2
extrude "Extrude14" cut of existing geometry blind -7
extrude "Extrude15" add of existing geometry to an object
extrude "Extrude16" new body of existing geometry blind -3
sketch "Sketch6" plane through (-24, 0, 0) normal (-1, 0, 0) x axis (0, -1, 0)
  line L1 (-15.9277, 116.7956) -> (-15.9277, 176)
  line L2 (-21.6307, 116.7956) -> (-15.9277, 116.7956)
  line L3 (-21.6307, 110.325) -> (-21.6307, 116.7956)
  line L4 (-42.326, 110.325) -> (-21.6307, 110.325)
  line L5 (-42.326, 116.7956) -> (-42.326, 110.325)
  line L6 (-48.9277, 116.7956) -> (-42.326, 116.7956)
  line L7 (-48.9277, 176) -> (-48.9277, 116.7956)
  line L8 (-15.9277, 176) -> (-48.9277, 176)
  curve K1 (35.395, 253.2053) -> (39.3474, 235.851)
  line L9 (-53, 253.2053) -> (35.395, 253.2053)
  line L10 (-53, 28) -> (-53, 253.2053)
  line L11 (-33, 28) -> (-53, 28)
  line L12 (-2.8201, 28) -> (-33, 28)
  line L13 (-35, 194) -> (-35, 213)
  line L14 (-42, 194) -> (-35, 194)
  line L15 (-42, 213) -> (-42, 194)
  line L16 (-35, 213) -> (-42, 213)
  line L17 (-14.5, 105.4339) -> (-50.5, 105.4339)
  line L18 (-50.5, 176) -> (-50.5, 105.4339)
  line L19 (-14.5, 176) -> (-50.5, 176)
  line L20 (-14.5, 105.4339) -> (-14.5, 176)
  curve K2 (-25.2655, 144.5781) -> (-27.9943, 141.8305)
  line L21 (-25.2773, 147.9781) -> (-25.2655, 144.5781)
  curve K3 (-28.0249, 150.7069) -> (-25.2773, 147.9781)
  line L22 (-31.5199, 150.6948) -> (-28.0249, 150.7069)
  curve K4 (-34.2486, 147.9471) -> (-31.5199, 150.6948)
  line L23 (-34.2369, 144.5472) -> (-34.2486, 147.9471)
  curve K5 (-31.4893, 141.8184) -> (-34.2369, 144.5472)
  line L24 (-27.9943, 141.8305) -> (-31.4893, 141.8184)
  curve K6 (-25.2925, 156.805) -> (-28.0307, 154.0668)
  line L25 (-25.2925, 160.205) -> (-25.2925, 156.805)
  curve K7 (-28.0307, 162.9432) -> (-25.2925, 160.205)
  line L26 (-31.5257, 162.9432) -> (-28.0307, 162.9432)
  curve K8 (-34.2639, 160.205) -> (-31.5257, 162.9432)
  line L27 (-34.2639, 156.805) -> (-34.2639, 160.205)
  curve K9 (-31.5257, 154.0668) -> (-34.2639, 156.805)
  line L28 (-28.0307, 154.0668) -> (-31.5257, 154.0668)
  line L29 (-41.6307, 181.8352) -> (-41.6307, 154.9217)
  line L30 (-41.6307, 169.8352) -> (-41.6307, 181.8352)
  line L31 (-41.6307, 169.8352) -> (-41.6307, 159.8352)
  line L32 (-41.6307, 105.6182) -> (-41.6307, 159.8352)
  line L33 (-41.6307, 154.9217) -> (-41.6307, 105.6182)
  line L34 (-41.6307, 143.6792) -> (-41.6307, 146.6792)
  line L35 (-41.6307, 143.6792) -> (-41.6307, 146.6792)
  line L36 (-41.6307, 113.6182) -> (-41.6307, 161.8352)
  line L37 (-41.6307, 161.8352) -> (-41.6307, 113.6182)
  line L38 (-8.3223, 178) -> (-51, 178)
  line L39 (-8.3223, 97.2423) -> (-8.3223, 178)
  line L40 (-51, 97.2423) -> (-8.3223, 97.2423)
  line L41 (-51, 178) -> (-51, 97.2423)
  line L42 (-5, 95.1037) -> (-51, 95.1037)
  line L43 (-5, 185) -> (-5, 95.1037)
  line L44 (-51, 185) -> (-5, 185)
  line L45 (-51, 95.1037) -> (-51, 185)
  circle C1 centre (-19.6307, 107.155) radius 1.4
  circle C2 centre (-45.6307, 107.155) radius 1.4
  arc A1 centre (-2.8201, 80) radius 52 clockwise from (40.4895, 108.7798) to (-2.8201, 28)
  arc A2 centre (82.1333, 136.4527) radius 50 clockwise from (40.4895, 108.7798) to (32.1436, 135.4388)
  arc A3 centre (1.7685, 134.8228) radius 30.3814 clockwise from (31.815, 139.3208) to (32.1436, 135.4388)
  arc A4 centre (81.264, 146.7234) radius 50 clockwise from (31.815, 139.3208) to (40.632, 175.8617)
  arc A5 centre (0, 205) radius 50 clockwise from (39.3474, 235.851) to (40.632, 175.8617)
  horizontal L38
  vertical L39
  horizontal L40
  vertical L41
  horizontal L42
  vertical L43
  horizontal L44
  vertical L45
extrude "Extrude17" add of existing geometry blind 5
